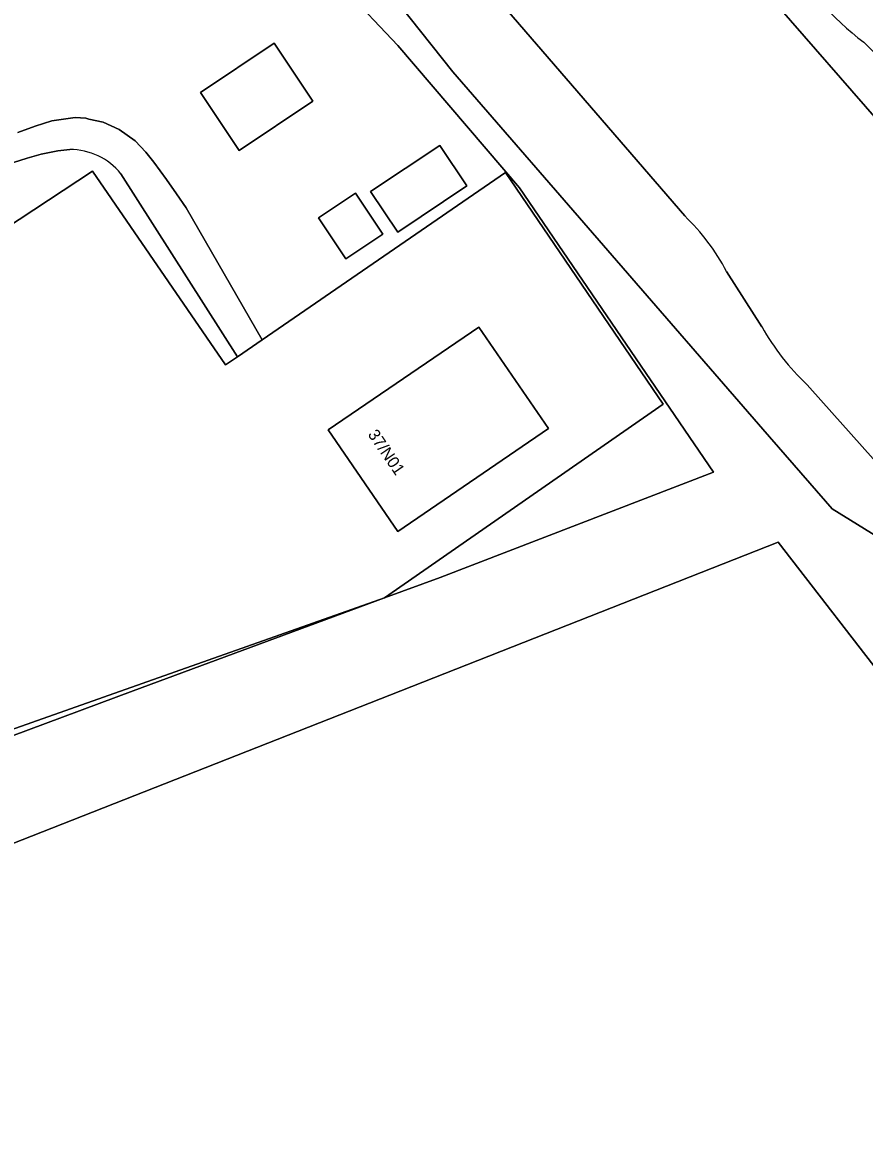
# Model space of a CAD drawing. Extents: x 156661 to 157576, y 383570 to 384425.
# Drawn here: x 157294 to 157365.7, y 383711.1 to 383806.8 of the extents above; entities that cross this region are included whole.
import ezdxf

# ---------------------------------------------------------------- set-up
doc = ezdxf.new("R2010")
doc.units = 0
for name, color, linetype in [('IMGEO_Erf', 7, 'Continuous'), ('IMGEO_Gemengd_bos', 7, 'Continuous'), ('IMGEO_Grasland_overig', 7, 'Continuous'), ('IMGEO_Groenvoorziening', 7, 'Continuous'), ('IMGEO_Hek', 7, 'Continuous'), ('IMGEO_Pand', 7, 'Continuous'), ('IMGEO_Pand_nummerreeks', 7, 'Continuous'), ('IMGEO_Rijbaan_lokaal_halfverhard', 7, 'Continuous'), ('IMGEO_Terreindeel_open', 7, 'Continuous')]:
    doc.layers.add(name, color=color, linetype=linetype)

msp = doc.modelspace()

# ---------------------------------------------------------------- linework, layer by layer
at = {"layer": 'IMGEO_Erf'}
for points in [[(157324.866, 383757.87), (157348.567, 383774.345), (157335.149, 383794.067), (157314.431, 383779.837), (157312.332, 383778.396), (157311.319, 383777.7), (157300.001, 383794.175), (157221.789, 383742.655), (157226.005, 383735.606), (157229.305, 383730.173), (157232.472, 383725.228)], [(157320.072, 383772.164), (157332.875, 383780.917), (157338.794, 383772.285), (157325.988, 383763.521)]]:
    msp.add_lwpolyline(points, close=True, dxfattribs=at)
at = {"layer": 'IMGEO_Gemengd_bos'}
for points in [[(157314.185, 383853.421), (157312.496, 383856.87), (157309.262, 383862.615), (157310.784, 383853.456), (157315.282, 383842.52), (157316.304, 383837.205), (157316.21, 383828.929), (157323.175, 383821.921), (157350.404, 383790.373)], [(157350.404, 383790.373), (157323.175, 383821.921), (157316.21, 383828.929), (157313, 383828.77)], [(157310.286, 383826.493), (157311.611, 383824.367), (157318.535, 383817.641), (157323.394, 383811.806), (157330.662, 383802.648), (157357.052, 383772.239), (157362.946, 383765.447), (157373.346, 383759.004)], [(157400.397, 383760.458), (157396.047, 383767.014), (157382.443, 383783.251), (157376.416, 383789.142), (157366.752, 383798.589), (157358.422, 383808.104), (157356.218, 383811.537), (157354.454, 383814.745), (157352.073, 383817.521), (157348.687, 383820.55)], [(157373.346, 383759.004), (157362.946, 383765.447), (157357.052, 383772.239), (157330.662, 383802.648), (157323.394, 383811.806)], [(157321.415, 383809.74), (157325.982, 383804.89), (157336.335, 383792.758), (157352.852, 383768.572), (157329.601, 383759.614), (157324.866, 383757.87), (157303.453, 383749.98), (157275.261, 383739.464), (157245.186, 383727.961), (157225.784, 383720.815), (157231.842, 383711.326), (157232.486, 383711.598), (157285.189, 383733.84), (157326.234, 383749.98), (157358.346, 383762.608), (157368.143, 383749.98)], [(157356.972, 383780.953), (157353.967, 383785.636)], [(157353.967, 383785.636), (157356.972, 383780.953)], [(157366.428, 383769.72), (157361.059, 383775.737), (157360.814, 383776.012)], [(157360.814, 383776.012), (157361.059, 383775.737), (157366.428, 383769.72)], [(157381.207, 383680.69), (157394.48, 383676.444), (157398.069, 383669.046), (157409.138, 383666.082), (157412.12, 383680.62), (157406.857, 383688.859), (157405.202, 383690.908), (157403.342, 383692.773), (157393.317, 383702.255), (157391.63, 383719.705), (157368.143, 383749.98), (157358.346, 383762.608), (157326.234, 383749.98), (157285.189, 383733.84), (157232.486, 383711.598), (157231.842, 383711.326), (157239.82, 383698.833), (157242.24, 383695.049), (157250.444, 383682.213)]]:
    msp.add_lwpolyline(points, dxfattribs=at)
for centre, radius, start, end in [((157379.413, 383823.536), 22.97, 207.66968, 233.17005), ((157256.186, 383692.399), 157.143, 38.82019, 45.84922), ((157337.614, 383777.045), 18.472, 27.71667, 46.18165), ((157337.614, 383777.045), 18.472, 27.71667, 46.18165), ((157374.224, 383790.404), 19.671, 208.7136, 227.02192), ((157374.224, 383790.404), 19.671, 208.7136, 227.02192)]:
    msp.add_arc(centre, radius, start, end, dxfattribs=at)
at = {"layer": 'IMGEO_Grasland_overig'}
msp.add_lwpolyline([(157348.687, 383820.55), (157352.073, 383817.521), (157354.454, 383814.745), (157356.218, 383811.537), (157358.422, 383808.104), (157366.752, 383798.589), (157376.416, 383789.142), (157382.443, 383783.251), (157396.047, 383767.014), (157400.397, 383760.458)], dxfattribs=at)
for centre, radius, start, end in [((157379.413, 383823.536), 22.97, 207.66968, 233.17005), ((157256.186, 383692.399), 157.143, 38.82019, 45.84922)]:
    msp.add_arc(centre, radius, start, end, dxfattribs=at)
at = {"layer": 'IMGEO_Groenvoorziening'}
for points in [[(157293.653, 383797.464), (157295.132, 383798.016), (157296.543, 383798.457), (157298.537, 383798.738), (157299.444, 383798.681), (157299.702, 383798.622), (157300.905, 383798.343), (157302.286, 383797.728), (157303.637, 383796.759), (157304.532, 383795.812), (157305.211, 383794.943), (157306.293, 383793.464), (157307.14, 383792.267), (157307.979, 383791.064), (157314.431, 383779.837), (157335.149, 383794.067), (157348.567, 383774.345), (157324.866, 383757.87), (157329.601, 383759.614), (157352.852, 383768.572), (157336.335, 383792.758), (157325.982, 383804.89), (157321.415, 383809.74)], [(157298.075, 383796.028), (157297.044, 383795.919), (157295.639, 383795.619), (157294.458, 383795.281), (157293.292, 383794.914), (157292.131, 383794.565), (157290.982, 383794.25), (157289.625, 383794.078), (157288.594, 383794.052), (157287.384, 383794.141), (157286.634, 383794.259), (157282.252, 383791.413), (157222.91, 383750), (157213.385, 383743.353), (157215.866, 383739.273), (157221.789, 383742.655), (157300.001, 383794.175)], [(157300.001, 383794.175), (157311.319, 383777.7), (157312.332, 383778.396), (157302.426, 383793.969)]]:
    msp.add_lwpolyline(points, dxfattribs=at)
for points in [[(157315.469, 383805.079), (157318.765, 383800.146), (157312.479, 383795.947), (157309.183, 383800.88)], [(157323.668, 383792.451), (157329.552, 383796.382), (157331.858, 383792.931), (157325.974, 383789)], [(157322.384, 383792.307), (157324.708, 383788.828), (157321.556, 383786.722), (157319.232, 383790.2)], [(157231.747, 383725.831), (157225.605, 383721.905), (157222.954, 383726.182), (157222.557, 383725.869), (157225.784, 383720.815), (157245.186, 383727.961), (157275.261, 383739.464), (157303.453, 383749.98), (157324.866, 383757.87), (157232.472, 383725.228), (157229.305, 383730.173), (157229.21, 383730.122)]]:
    msp.add_lwpolyline(points, close=True, dxfattribs=at)
msp.add_arc((157298.08, 383790.413), 5.615, 39.29494, 90.05573, dxfattribs=at)
at = {"layer": 'IMGEO_Hek'}
for points in [[(157326.234, 383749.98), (157358.346, 383762.608), (157368.143, 383749.98)], [(157326.234, 383749.98), (157285.189, 383733.84), (157232.486, 383711.598)]]:
    msp.add_lwpolyline(points, dxfattribs=at)
at = {"layer": 'IMGEO_Pand'}
msp.add_lwpolyline([(157325.988, 383763.521), (157338.794, 383772.285), (157332.875, 383780.917), (157320.072, 383772.164)], close=True, dxfattribs=at)
at = {"layer": 'IMGEO_Rijbaan_lokaal_halfverhard'}
for points in [[(157302.426, 383793.969), (157312.332, 383778.396), (157314.431, 383779.837), (157307.979, 383791.064), (157307.14, 383792.267), (157306.293, 383793.464), (157305.211, 383794.943), (157304.532, 383795.812), (157303.637, 383796.759), (157302.286, 383797.728), (157300.905, 383798.343), (157299.702, 383798.622), (157299.444, 383798.681), (157298.537, 383798.738), (157296.543, 383798.457), (157295.132, 383798.016), (157293.653, 383797.464)], [(157278.101, 383796.981), (157279.338, 383796.445), (157280.335, 383796.042), (157281.47, 383795.622), (157282.619, 383795.24), (157283.785, 383794.896), (157284.983, 383794.588), (157286.172, 383794.331), (157286.634, 383794.259), (157287.384, 383794.141), (157288.594, 383794.052), (157289.625, 383794.078), (157290.982, 383794.25), (157292.131, 383794.565), (157293.292, 383794.914), (157294.458, 383795.281)], [(157294.458, 383795.281), (157295.639, 383795.619), (157297.044, 383795.919), (157298.075, 383796.028)]]:
    msp.add_lwpolyline(points, dxfattribs=at)
msp.add_arc((157298.08, 383790.413), 5.615, 39.29494, 90.05573, dxfattribs=at)
at = {"layer": 'IMGEO_Terreindeel_open'}
for points in [[(157312.479, 383795.947), (157318.765, 383800.146), (157315.469, 383805.079), (157309.183, 383800.88)], [(157323.668, 383792.451), (157325.974, 383789), (157331.858, 383792.931), (157329.552, 383796.382)], [(157324.708, 383788.828), (157322.384, 383792.307), (157319.232, 383790.2), (157321.556, 383786.722)]]:
    msp.add_lwpolyline(points, close=True, dxfattribs=at)

# ---------------------------------------------------------------- texts
at = {"layer": 'IMGEO_Pand_nummerreeks'}
msp.add_text('37/N01', height=1, rotation=304.36786, dxfattribs=at).set_placement((157323.39, 383771.781))

doc.saveas('drawing.dxf')
